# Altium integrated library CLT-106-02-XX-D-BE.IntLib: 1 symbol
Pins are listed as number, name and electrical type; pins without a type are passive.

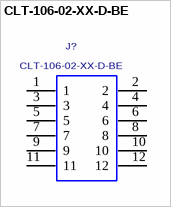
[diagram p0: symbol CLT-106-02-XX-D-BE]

## CLT-106-02-XX-D-BE
designator J?
LOW PROFILE SOCKET STRIP, 2mm PITCH, BOTTOM ENTRY, 12 PINS.; MANUFACTURER: SAMTEC
footprint CLT-106-02-XX-D-BE
pins: 1, 2, 3, 4, 5, 6, 7, 8, 9, 10, 11, 12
